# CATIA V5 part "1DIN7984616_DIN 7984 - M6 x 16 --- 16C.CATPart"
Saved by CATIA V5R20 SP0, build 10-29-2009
Part number: 1DIN7984616_DIN 7984 - M6 x 16 --- 16C
Revision: ANY
Definition: UNKNOWN
Nomenclature: 1DIN7984616_DIN 7984 - M6 x 16 --- 16C
Source: Unknown
Bounding box of the stored display mesh (mm): x 0 to 20, y -5 to 5, z -5 to 5
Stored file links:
  C:\Users\Utente\Desktop\IO LAVORO\3D X SITO CF\CUMSA\3D files PW\pw101830\pw101830_ejection\1DIN7984616_DIN 7984 - M6 x 16 --- 16C.CATPart
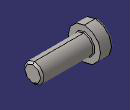
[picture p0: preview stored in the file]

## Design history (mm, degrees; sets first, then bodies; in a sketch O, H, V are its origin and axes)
Body1 "Hex" (main body)
  Solid1: solid without history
